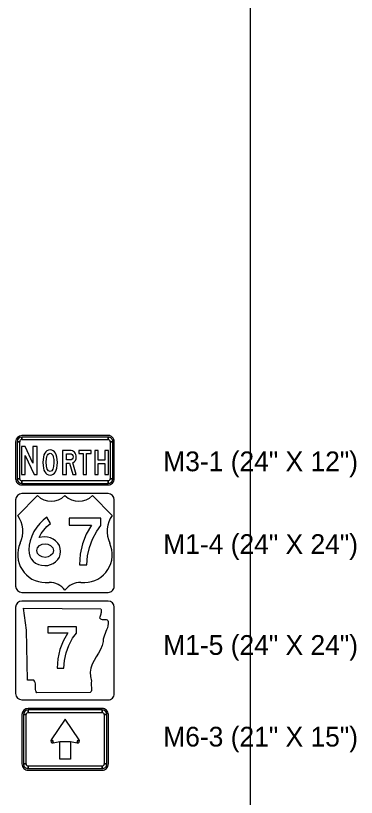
# Model space of a CAD drawing. Extents: x 1001568 to 1002149, y 1840825 to 1841423.
# Drawn here: x 1001915.9 to 1001922.8, y 1841178.92 to 1841194.75 of the extents above; entities that cross this region are included whole.
import ezdxf

# ---------------------------------------------------------------- set-up
doc = ezdxf.new("R2010")
doc.units = 0
for name, color, linetype in [('40', 7, 'Continuous'), ('R_No Plot', 7, 'Continuous'), ('SIGNS', 7, 'Continuous')]:
    doc.layers.add(name, color=color, linetype=linetype)

msp = doc.modelspace()

# ---------------------------------------------------------------- linework, layer by layer
at = {"layer": 'R_No Plot'}
msp.add_line((1001920.65, 1841210.667), (1001920.65, 1841148.127), dxfattribs=at)
at = {"layer": 'SIGNS'}
for p, q in [((1001917.774, 1841186.244), (1001916.024, 1841186.244)), ((1001916.024, 1841186.161), (1001916.024, 1841186.213)), ((1001917.774, 1841186.213), (1001917.774, 1841186.161)), ((1001915.899, 1841186.119), (1001915.899, 1841185.369)), ((1001915.931, 1841186.119), (1001915.983, 1841186.119)), ((1001917.816, 1841186.119), (1001917.868, 1841186.119)), ((1001917.899, 1841185.369), (1001917.899, 1841186.119)), ((1001915.983, 1841185.369), (1001915.931, 1841185.369)), ((1001916.024, 1841185.275), (1001916.024, 1841185.327)), ((1001916.024, 1841185.244), (1001917.774, 1841185.244)), ((1001917.774, 1841185.327), (1001917.774, 1841185.275)), ((1001917.868, 1841185.369), (1001917.816, 1841185.369)), ((1001915.899, 1841184.943), (1001915.899, 1841183.193)), ((1001916.34, 1841185.027), (1001915.941, 1841184.627)), ((1001917.774, 1841185.068), (1001916.024, 1841185.068)), ((1001917.858, 1841184.627), (1001917.458, 1841185.027)), ((1001917.899, 1841183.193), (1001917.899, 1841184.943)), ((1001915.899, 1841183.193), (1001915.899, 1841183.193)), ((1001916.5, 1841183.27), (1001916.58, 1841183.27)), ((1001917.219, 1841183.27), (1001917.299, 1841183.27)), ((1001916.024, 1841183.068), (1001917.774, 1841183.068)), ((1001917.774, 1841182.893), (1001916.024, 1841182.893)), ((1001915.899, 1841182.768), (1001915.899, 1841181.018)), ((1001917.899, 1841181.018), (1001917.899, 1841182.768)), ((1001915.899, 1841181.018), (1001915.899, 1841181.018)), ((1001916.024, 1841180.893), (1001917.774, 1841180.893)), ((1001917.653, 1841180.719), (1001916.153, 1841180.719)), ((1001916.153, 1841180.636), (1001916.153, 1841180.688)), ((1001917.653, 1841180.688), (1001917.653, 1841180.636)), ((1001916.028, 1841180.594), (1001916.028, 1841179.594)), ((1001916.059, 1841180.594), (1001916.112, 1841180.594)), ((1001917.695, 1841180.594), (1001917.747, 1841180.594)), ((1001917.778, 1841179.594), (1001917.778, 1841180.594)), ((1001916.653, 1841180.063), (1001916.618, 1841180.085)), ((1001916.663, 1841180.022), (1001916.653, 1841180.063)), ((1001917.153, 1841180.063), (1001917.144, 1841180.022)), ((1001917.188, 1841180.085), (1001917.153, 1841180.063)), ((1001916.112, 1841179.594), (1001916.059, 1841179.594)), ((1001916.153, 1841179.5), (1001916.153, 1841179.552)), ((1001917.653, 1841179.552), (1001917.653, 1841179.5)), ((1001917.747, 1841179.594), (1001917.695, 1841179.594)), ((1001916.153, 1841179.469), (1001917.653, 1841179.469))]:
    msp.add_line(p, q, dxfattribs=at)
for points in [[(1001917.774, 1841186.213), (1001916.024, 1841186.213), (1001916.024, 1841186.161), (1001917.774, 1841186.161), (1001917.774, 1841186.213), (1001917.774, 1841186.213)], [(1001915.931, 1841186.119), (1001915.931, 1841185.369), (1001915.983, 1841185.369), (1001915.983, 1841186.119), (1001915.931, 1841186.119), (1001915.931, 1841186.119)], [(1001917.868, 1841185.369), (1001917.868, 1841186.119), (1001917.816, 1841186.119), (1001917.816, 1841185.369), (1001917.868, 1841185.369), (1001917.868, 1841185.369)], [(1001916.015, 1841185.452), (1001916.093, 1841185.452), (1001916.093, 1841185.839), (1001916.274, 1841185.452), (1001916.338, 1841185.452), (1001916.338, 1841186.025), (1001916.25, 1841186.025), (1001916.25, 1841185.683), (1001916.093, 1841186.025), (1001916.015, 1841186.025)], [(1001917.266, 1841185.452), (1001917.338, 1841185.452), (1001917.338, 1841185.881), (1001917.429, 1841185.881), (1001917.429, 1841185.943), (1001917.177, 1841185.943), (1001917.177, 1841185.881), (1001917.266, 1841185.881)], [(1001917.504, 1841185.452), (1001917.571, 1841185.452), (1001917.571, 1841185.677), (1001917.706, 1841185.677), (1001917.706, 1841185.452), (1001917.781, 1841185.452), (1001917.781, 1841185.943), (1001917.706, 1841185.943), (1001917.706, 1841185.746), (1001917.571, 1841185.746), (1001917.571, 1841185.943), (1001917.504, 1841185.943)], [(1001916.024, 1841185.275), (1001917.774, 1841185.275), (1001917.774, 1841185.327), (1001916.024, 1841185.327), (1001916.024, 1841185.275), (1001916.024, 1841185.275)], [(1001917.192, 1841183.629), (1001917.344, 1841183.629), (1001917.356, 1841183.806), (1001917.393, 1841183.979), (1001917.455, 1841184.146), (1001917.542, 1841184.31), (1001917.625, 1841184.422), (1001917.625, 1841184.569), (1001916.981, 1841184.569), (1001916.981, 1841184.428), (1001917.435, 1841184.428), (1001917.33, 1841184.244), (1001917.255, 1841184.05), (1001917.209, 1841183.845)], [(1001917.629, 1841182.738), (1001917.634, 1841182.719), (1001917.636, 1841182.7), (1001917.635, 1841182.681), (1001917.633, 1841182.662), (1001917.629, 1841182.643), (1001917.624, 1841182.624), (1001917.618, 1841182.605), (1001917.612, 1841182.586), (1001917.607, 1841182.568), (1001917.602, 1841182.55), (1001917.616, 1841182.534), (1001917.634, 1841182.524), (1001917.653, 1841182.52), (1001917.675, 1841182.52), (1001917.696, 1841182.521), (1001917.717, 1841182.521), (1001917.736, 1841182.519), (1001917.752, 1841182.513), (1001917.766, 1841182.501), (1001917.774, 1841182.48), (1001917.774, 1841182.435), (1001917.769, 1841182.392), (1001917.758, 1841182.352), (1001917.743, 1841182.313), (1001917.728, 1841182.275), (1001917.712, 1841182.237), (1001917.697, 1841182.199), (1001917.685, 1841182.159), (1001917.676, 1841182.118), (1001917.674, 1841182.074), (1001917.652, 1841181.991), (1001917.618, 1841181.913), (1001917.578, 1841181.838), (1001917.534, 1841181.763), (1001917.49, 1841181.688), (1001917.453, 1841181.612), (1001917.425, 1841181.534), (1001917.41, 1841181.451), (1001917.414, 1841181.364), (1001917.439, 1841181.27), (1001917.432, 1841181.247), (1001917.429, 1841181.223), (1001917.43, 1841181.199), (1001917.433, 1841181.175), (1001917.436, 1841181.151), (1001917.439, 1841181.128), (1001917.439, 1841181.104), (1001917.436, 1841181.083), (1001917.428, 1841181.061), (1001917.412, 1841181.042), (1001916.329, 1841181.032), (1001916.314, 1841181.052), (1001916.306, 1841181.075), (1001916.302, 1841181.102), (1001916.302, 1841181.13), (1001916.302, 1841181.16), (1001916.303, 1841181.189), (1001916.301, 1841181.218), (1001916.295, 1841181.245), (1001916.284, 1841181.269), (1001916.265, 1841181.29), (1001916.139, 1841181.29), (1001916.121, 1841182.302), (1001916.058, 1841182.748), (1001917.629, 1841182.738), (1001917.629, 1841182.738)], [(1001916.742, 1841181.532), (1001916.878, 1841181.532), (1001916.889, 1841181.691), (1001916.922, 1841181.845), (1001916.977, 1841181.995), (1001917.055, 1841182.142), (1001917.13, 1841182.242), (1001917.13, 1841182.374), (1001916.553, 1841182.374), (1001916.553, 1841182.248), (1001916.959, 1841182.248), (1001916.865, 1841182.083), (1001916.798, 1841181.909), (1001916.757, 1841181.725)], [(1001917.653, 1841180.688), (1001916.153, 1841180.688), (1001916.153, 1841180.636), (1001917.653, 1841180.636), (1001917.653, 1841180.688), (1001917.653, 1841180.688)], [(1001916.059, 1841180.594), (1001916.059, 1841179.594), (1001916.112, 1841179.594), (1001916.112, 1841180.594), (1001916.059, 1841180.594), (1001916.059, 1841180.594)], [(1001916.903, 1841180.5), (1001916.618, 1841180.085), (1001916.653, 1841180.063), (1001916.663, 1841180.022), (1001916.794, 1841180.052), (1001917.013, 1841180.052), (1001917.144, 1841180.022), (1001917.153, 1841180.063), (1001917.188, 1841180.085), (1001916.903, 1841180.5), (1001916.903, 1841180.5)], [(1001917.747, 1841179.594), (1001917.747, 1841180.594), (1001917.695, 1841180.594), (1001917.695, 1841179.594), (1001917.747, 1841179.594), (1001917.747, 1841179.594)], [(1001917.013, 1841179.688), (1001916.794, 1841179.688), (1001916.794, 1841180.052), (1001917.013, 1841180.052), (1001917.013, 1841179.688), (1001917.013, 1841179.688)], [(1001916.153, 1841179.5), (1001917.653, 1841179.5), (1001917.653, 1841179.552), (1001916.153, 1841179.552), (1001916.153, 1841179.5), (1001916.153, 1841179.5)]]:
    msp.add_lwpolyline(points, close=True, dxfattribs=at)
for points in [[(1001916.745, 1841185.698), (1001916.742, 1841185.758), (1001916.735, 1841185.809), (1001916.724, 1841185.853), (1001916.708, 1841185.889), (1001916.688, 1841185.916), (1001916.663, 1841185.936), (1001916.633, 1841185.948), (1001916.6, 1841185.952), (1001916.565, 1841185.948), (1001916.535, 1841185.936), (1001916.51, 1841185.916), (1001916.489, 1841185.889), (1001916.473, 1841185.853), (1001916.462, 1841185.809), (1001916.455, 1841185.758), (1001916.453, 1841185.698), (1001916.455, 1841185.638), (1001916.462, 1841185.586), (1001916.473, 1841185.542), (1001916.489, 1841185.507), (1001916.509, 1841185.479), (1001916.534, 1841185.459), (1001916.563, 1841185.447), (1001916.597, 1841185.443), (1001916.631, 1841185.447), (1001916.661, 1841185.459), (1001916.687, 1841185.479), (1001916.708, 1841185.507), (1001916.724, 1841185.542), (1001916.735, 1841185.586), (1001916.742, 1841185.638), (1001916.745, 1841185.698)], [(1001916.674, 1841185.701), (1001916.669, 1841185.619), (1001916.655, 1841185.561), (1001916.631, 1841185.526), (1001916.597, 1841185.514), (1001916.563, 1841185.526), (1001916.539, 1841185.564), (1001916.525, 1841185.626), (1001916.52, 1841185.713), (1001916.523, 1841185.771), (1001916.532, 1841185.819), (1001916.543, 1841185.848), (1001916.558, 1841185.87), (1001916.576, 1841185.882), (1001916.597, 1841185.887), (1001916.618, 1841185.882), (1001916.636, 1841185.868), (1001916.651, 1841185.845), (1001916.662, 1841185.812), (1001916.671, 1841185.761), (1001916.674, 1841185.701)], [(1001916.851, 1841185.452), (1001916.928, 1841185.452), (1001916.928, 1841185.686), (1001916.993, 1841185.686), (1001917.057, 1841185.452), (1001917.127, 1841185.452), (1001917.056, 1841185.694), (1001917.087, 1841185.711), (1001917.11, 1841185.738), (1001917.123, 1841185.77), (1001917.127, 1841185.805), (1001917.125, 1841185.835), (1001917.119, 1841185.861), (1001917.109, 1841185.884), (1001917.094, 1841185.904), (1001917.075, 1841185.921), (1001917.053, 1841185.933), (1001917.027, 1841185.94), (1001916.997, 1841185.943), (1001916.851, 1841185.943), (1001916.851, 1841185.452)], [(1001916.928, 1841185.75), (1001916.928, 1841185.875), (1001916.999, 1841185.875), (1001917.025, 1841185.871), (1001917.045, 1841185.858), (1001917.058, 1841185.839), (1001917.062, 1841185.813), (1001917.058, 1841185.785), (1001917.047, 1841185.766), (1001917.028, 1841185.754), (1001917.002, 1841185.75), (1001916.928, 1841185.75)], [(1001915.899, 1841184.943), (1001915.899, 1841184.943)], [(1001916.024, 1841185.068), (1001916.024, 1841185.068)], [(1001917.774, 1841185.068), (1001917.774, 1841185.068)], [(1001916.608, 1841184.463), (1001916.532, 1841184.588), (1001916.457, 1841184.532), (1001916.389, 1841184.466), (1001916.327, 1841184.389), (1001916.271, 1841184.301), (1001916.225, 1841184.207), (1001916.192, 1841184.114), (1001916.172, 1841184.022), (1001916.166, 1841183.931), (1001916.172, 1841183.863), (1001916.189, 1841183.802), (1001916.217, 1841183.748), (1001916.256, 1841183.7), (1001916.305, 1841183.661), (1001916.36, 1841183.633), (1001916.421, 1841183.616), (1001916.489, 1841183.611), (1001916.55, 1841183.615), (1001916.607, 1841183.63), (1001916.66, 1841183.654), (1001916.709, 1841183.688), (1001916.754, 1841183.731), (1001916.785, 1841183.78), (1001916.804, 1841183.834), (1001916.81, 1841183.894), (1001916.804, 1841183.957), (1001916.785, 1841184.015), (1001916.753, 1841184.067), (1001916.708, 1841184.112), (1001916.658, 1841184.147), (1001916.603, 1841184.171), (1001916.542, 1841184.186), (1001916.477, 1841184.191), (1001916.375, 1841184.181), (1001916.418, 1841184.258), (1001916.471, 1841184.331), (1001916.534, 1841184.399), (1001916.608, 1841184.463)], [(1001916.332, 1841183.916), (1001916.345, 1841183.972), (1001916.385, 1841184.018), (1001916.438, 1841184.044), (1001916.496, 1841184.053), (1001916.555, 1841184.044), (1001916.608, 1841184.018), (1001916.65, 1841183.972), (1001916.664, 1841183.916), (1001916.65, 1841183.858), (1001916.608, 1841183.812), (1001916.556, 1841183.785), (1001916.496, 1841183.777), (1001916.437, 1841183.785), (1001916.385, 1841183.812), (1001916.345, 1841183.858), (1001916.332, 1841183.916)], [(1001916.024, 1841183.068), (1001916.024, 1841183.068)], [(1001917.774, 1841183.068), (1001917.774, 1841183.068)], [(1001916.024, 1841182.893), (1001916.024, 1841182.893)], [(1001917.774, 1841182.893), (1001917.774, 1841182.893)], [(1001915.899, 1841182.768), (1001915.899, 1841182.768)], [(1001916.024, 1841180.893), (1001916.024, 1841180.893)], [(1001917.774, 1841180.893), (1001917.774, 1841180.893)]]:
    msp.add_lwpolyline(points, dxfattribs=at)
for centre, radius, start, end in [((1001916.024, 1841186.119), 0.125, 90.0002, 179.9998), ((1001916.024, 1841186.119), 0.0937, 90.0002, 179.9998), ((1001917.774, 1841186.119), 0.125, 0, 90.0002), ((1001917.774, 1841186.119), 0.0937, 0, 90.0002), ((1001916.024, 1841186.119), 0.0417, 90.0002, 179.9998), ((1001917.774, 1841186.119), 0.0417, 0, 90.0002), ((1001916.024, 1841185.369), 0.125, 179.9998, 270.0001), ((1001916.024, 1841185.369), 0.0937, 179.9998, 270.0001), ((1001916.024, 1841185.369), 0.0417, 179.9998, 270.0001), ((1001917.774, 1841185.369), 0.125, 270.0001, 0.0003), ((1001917.774, 1841185.369), 0.0937, 270.0001, 0.0003), ((1001917.774, 1841185.369), 0.0417, 270.0001, 0.0003), ((1001916.024, 1841184.943), 0.125, 90.0002, 179.9998), ((1001916.62, 1841185.312), 0.399, 225.5729, 314.4272), ((1001917.179, 1841185.312), 0.399, 225.5729, 314.4272), ((1001917.774, 1841184.943), 0.125, 0, 90), ((1001915.487, 1841184.302), 0.559, 334.9895, 35.6629), ((1001918.312, 1841184.302), 0.559, 144.3372, 205.01), ((1001916.5, 1841183.829), 0.559, 154.9897, 270.0001), ((1001917.299, 1841183.829), 0.559, 270.0001, 25.0104), ((1001916.024, 1841183.193), 0.125, 180, 270), ((1001916.58, 1841182.871), 0.399, 36.8699, 90.0002), ((1001917.219, 1841182.871), 0.399, 90.0002, 143.13), ((1001917.774, 1841183.193), 0.125, 270.0001, 0.0003), ((1001916.024, 1841182.768), 0.125, 90.0002, 179.9998), ((1001917.774, 1841182.768), 0.125, 0, 90), ((1001916.024, 1841181.018), 0.125, 180, 270), ((1001917.774, 1841181.018), 0.125, 270.0001, 0.0003), ((1001916.153, 1841180.594), 0.125, 90.0002, 179.9998), ((1001916.153, 1841180.594), 0.0937, 90.0002, 179.9998), ((1001917.653, 1841180.594), 0.125, 0, 90.0002), ((1001917.653, 1841180.594), 0.0937, 0, 90.0002), ((1001916.153, 1841180.594), 0.0417, 90.0002, 179.9998), ((1001917.653, 1841180.594), 0.0417, 0, 90.0002), ((1001916.653, 1841180.063), 0.0417, 147.7246, 282.9506), ((1001917.153, 1841180.063), 0.0417, 257.0495, 32.2756), ((1001916.153, 1841179.594), 0.125, 179.9998, 270.0001), ((1001916.153, 1841179.594), 0.0937, 179.9998, 270.0001), ((1001916.153, 1841179.594), 0.0417, 179.9998, 270.0001), ((1001917.653, 1841179.594), 0.0937, 270.0001, 0.0003), ((1001917.653, 1841179.594), 0.0417, 270.0001, 0.0003), ((1001917.653, 1841179.594), 0.125, 270.0001, 0.0003)]:
    msp.add_arc(centre, radius, start, end, dxfattribs=at)

# ---------------------------------------------------------------- texts
at = {"layer": '40'}
for s, p in [('M3-1 (24" X 12")', (1001918.89, 1841185.521)), ('M1-4 (24" X 24")', (1001918.89, 1841183.846)), ('M1-5 (24" X 24")', (1001918.89, 1841181.803)), ('M6-3 (21" X 15")', (1001918.89, 1841179.947))]:
    msp.add_text(s, height=0.4, rotation=0, dxfattribs=at).set_placement(p)

doc.saveas('drawing.dxf')
